// Mitsubishi GX Works2 project: MC-35MR-4MT-F700-FX-C(0224)L   PLC: FX1S

PROGRAM MAIN
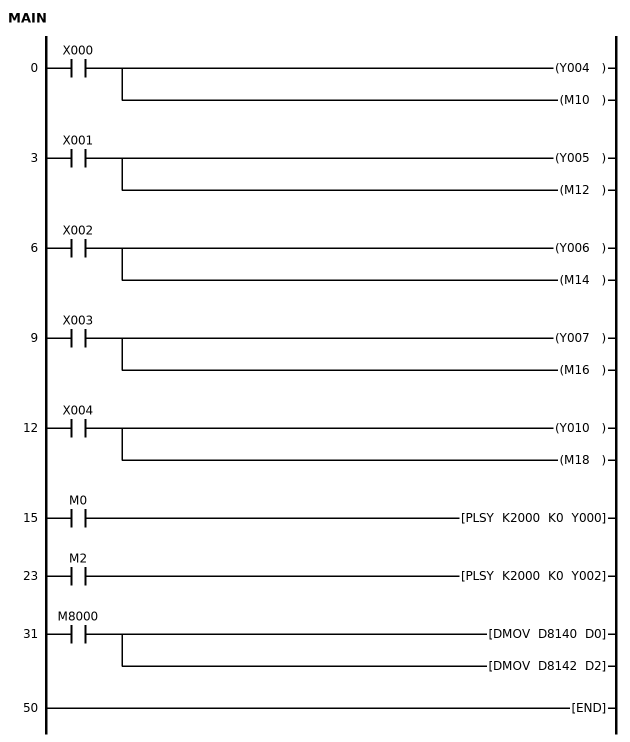
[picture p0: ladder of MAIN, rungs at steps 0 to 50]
0     LD      X000
      OUT     Y004
      OUT     M10
3     LD      X001
      OUT     Y005
      OUT     M12
6     LD      X002
      OUT     Y006
      OUT     M14
9     LD      X003
      OUT     Y007
      OUT     M16
12    LD      X004
      OUT     Y010
      OUT     M18
15    LD      M0
      PLSY    K2000 K0 Y000
23    LD      M2
      PLSY    K2000 K0 Y002
31    LD      M8000
      DMOV    D8140 D0
      DMOV    D8142 D2
50    END
END_PROGRAM
